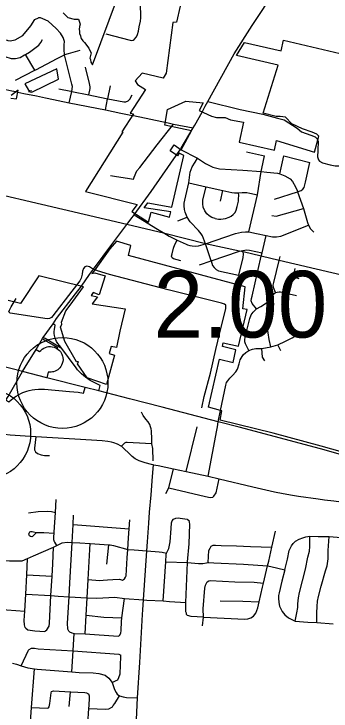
# Model space of a CAD drawing. Extents: x 1659811 to 1934326, y 644115 to 934867.
# Drawn here: x 1806794 to 1812018, y 688370 to 699875 of the extents above; entities that cross this region are included whole.
import ezdxf

# ---------------------------------------------------------------- set-up
doc = ezdxf.new("R2010")
doc.units = 0
for name, color, linetype in [('Default', 7, 'Continuous'), ('GM_X_City_Street', 7, 'Continuous'), ('GM_X_Corporation', 7, 'Continuous'), ('GM_X_County_Road', 7, 'Continuous'), ('GM_X_Interchange_Ramps', 7, 'Continuous'), ('GM_X_Interstate_Route', 7, 'Continuous'), ('GM_X_Township', 7, 'Continuous'), ('GM_X_Township_Road', 7, 'Continuous'), ('GM_X_US_Route', 7, 'Continuous')]:
    doc.layers.add(name, color=color, linetype=linetype)

msp = doc.modelspace()

# ---------------------------------------------------------------- linework, layer by layer
at = {"layer": 'Default'}
for centre in [(1807592, 693785), (1806318, 692948)]:
    msp.add_circle(centre, 750, dxfattribs=at)
at = {"layer": 'GM_X_City_Street'}
for points in [[(1808777, 699453), (1808814, 699499), (1808832, 699538), (1808844, 699592), (1808857, 699662), (1808877, 699755), (1808884, 699811), (1808886, 699883), (1808868, 700213), (1808881, 700265), (1808924, 700410), (1808950, 700522), (1809014, 700652)], [(1805586, 699203), (1805701, 699308), (1805749, 699339), (1805806, 699360), (1805921, 699380), (1805973, 699385), (1806322, 699422), (1806592, 699450), (1806680, 699441), (1806692, 699439), (1806732, 699433), (1806816, 699448), (1806942, 699519), (1807071, 699679), (1807140, 699782), (1807200, 699811)], [(1807705, 698411), (1807745, 698595), (1807756, 698677), (1807749, 698714), (1807690, 698934), (1807627, 699202), (1807625, 699208), (1807623, 699283), (1807622, 699367), (1807624, 699419), (1807603, 699488), (1807562, 699557), (1807492, 699637), (1807421, 699698), (1807358, 699756), (1807268, 699794), (1807230, 699811), (1807200, 699811)], [(1806970, 699199), (1806972, 699200), (1806986, 699208), (1807049, 699244), (1807201, 699362), (1807234, 699403), (1807265, 699453)], [(1808309, 699546), (1808711, 699442), (1808727, 699439), (1808759, 699445), (1808777, 699453)], [(1807140, 698949), (1806986, 699208)], [(1807626, 699202), (1807627, 699202), (1807631, 699204), (1807690, 699223), (1807883, 699275)], [(1806643, 699171), (1806748, 699142), (1806822, 699140), (1806894, 699155), (1806970, 699199)], [(1807151, 698955), (1807152, 698955), (1807504, 699139), (1807626, 699202)], [(1808030, 698543), (1808051, 698644), (1808048, 698670), (1808039, 698726), (1807974, 698996)], [(1806819, 698781), (1807140, 698949), (1807151, 698955)], [(1806536, 698655), (1806554, 698652), (1806759, 698606), (1806794, 698599)], [(1807535, 698641), (1807729, 698599)], [(1808337, 698469), (1808339, 698475), (1808385, 698691)], [(1806846, 698589), (1806856, 698586), (1806957, 698564), (1807168, 698522), (1807312, 698491)], [(1807729, 698599), (1807745, 698595), (1808030, 698543), (1808311, 698481)], [(1808311, 698481), (1808339, 698475), (1808604, 698423), (1808639, 698424), (1808675, 698440), (1808701, 698470), (1808744, 698541)], [(1807312, 698491), (1807342, 698485), (1807705, 698411), (1808302, 698291), (1808557, 698239)], [(1808302, 698291), (1808337, 698469)], [(1808557, 698239), (1808748, 698201), (1808764, 698197)], [(1809334, 698076), (1809425, 698057), (1809749, 697995)], [(1811791, 697808), (1811807, 697776), (1811801, 697621), (1811793, 697519), (1811810, 697469), (1811828, 697447), (1811876, 697420), (1812006, 697385), (1812086, 697370), (1812158, 697370), (1812246, 697351), (1812348, 697334), (1812465, 697343), (1812495, 697343), (1812529, 697331), (1812575, 697318), (1812623, 697304), (1812628, 697303), (1812634, 697302)], [(1809536, 697637), (1809820, 697493), (1809950, 697406), (1810071, 697349), (1810183, 697321), (1810566, 697297), (1810867, 697273), (1810960, 697266), (1811138, 697249), (1811174, 697236), (1811256, 697206), (1811344, 697153), (1811382, 697108), (1811431, 697024), (1811463, 696951), (1811465, 696940), (1811563, 696665), (1811628, 696432), (1811648, 696387), (1811682, 696326), (1811732, 696271)], [(1810626, 697602), (1810924, 697531)], [(1810042, 695801), (1809948, 696080), (1809900, 696211), (1809876, 696247), (1809835, 696302), (1809699, 696445), (1809645, 696520), (1809613, 696606), (1809603, 696650), (1809597, 696708), (1809598, 696751), (1809608, 696803), (1809677, 697087), (1809696, 697264), (1809731, 697352), (1809779, 697429), (1809820, 697493)], [(1810878, 697323), (1810878, 697327), (1810924, 697531)], [(1811174, 697236), (1811241, 697531), (1811669, 697421)], [(1811465, 696940), (1811527, 696961), (1811553, 696983), (1811573, 697009), (1811596, 697101), (1811669, 697421)], [(1810664, 696278), (1810805, 696889), (1810867, 697273), (1810878, 697323)], [(1809677, 697087), (1809958, 697020), (1810235, 696959), (1810382, 696928), (1810430, 696924), (1810493, 696924), (1810553, 696930), (1810629, 696927), (1810682, 696920), (1810805, 696889)], [(1810110, 696497), (1810056, 696518), (1810011, 696545), (1809974, 696578), (1809938, 696628), (1809913, 696685), (1809904, 696742), (1809907, 696808), (1809958, 697020)], [(1810110, 696497), (1810165, 696488), (1810200, 696487), (1810238, 696491), (1810279, 696500), (1810337, 696521), (1810373, 696539), (1810403, 696563), (1810436, 696599), (1810455, 696635), (1810471, 696697), (1810491, 696786), (1810496, 696826), (1810497, 696879), (1810493, 696924)], [(1810197, 696788), (1810235, 696959)], [(1811085, 696820), (1811465, 696940)], [(1811042, 696550), (1811112, 696536), (1811563, 696665)], [(1808776, 696560), (1809158, 696323), (1809281, 696250), (1809353, 696207), (1809483, 696144), (1809629, 696074), (1809653, 696065), (1809693, 696053), (1809732, 696046), (1809788, 696042), (1809834, 696046), (1809948, 696080), (1810443, 696251), (1810541, 696275), (1810610, 696279), (1810664, 696278), (1810792, 696253), (1810951, 696217), (1811053, 696197), (1811120, 696197), (1811189, 696208), (1811648, 696387)], [(1809495, 696459), (1809645, 696520)], [(1810790, 695006), (1810718, 695098), (1810703, 695139), (1810706, 695177), (1810716, 695219), (1810869, 695876), (1810883, 695934), (1810951, 696217)], [(1809541, 695798), (1809422, 695835), (1809401, 695852), (1809391, 695878), (1809398, 695914), (1809423, 696009), (1809445, 696070), (1809483, 696144)], [(1810044, 695802), (1810511, 695961), (1810564, 695973), (1810631, 695982), (1810675, 695978), (1810883, 695934)], [(1810492, 695563), (1810507, 695584), (1810570, 695857), (1810577, 695908), (1810570, 695947), (1810564, 695973)], [(1811101, 695276), (1811068, 695358), (1811066, 695398), (1811076, 695444), (1811163, 695807), (1811180, 695872)], [(1809849, 695737), (1810042, 695801), (1810044, 695802)], [(1810042, 695801), (1810067, 695722), (1810091, 695691), (1810127, 695660), (1810166, 695638), (1810492, 695563)], [(1808072, 695681), (1808037, 695704), (1807997, 695711), (1807963, 695701), (1807941, 695673), (1807925, 695628), (1807918, 695580), (1807899, 695512), (1807877, 695473), (1807825, 695401), (1807748, 695302)], [(1811328, 695254), (1811397, 695534), (1811426, 695673)], [(1811397, 695534), (1811490, 695511)], [(1810663, 694319), (1810639, 694362), (1810608, 694428), (1810599, 694464), (1810598, 694497), (1810604, 694539), (1810682, 694851), (1810704, 694907), (1810736, 694952), (1810790, 695006), (1810864, 695047), (1810940, 695094), (1810975, 695126), (1811001, 695158), (1811043, 695227), (1811074, 695258), (1811101, 695276)], [(1811101, 695276), (1811130, 695285), (1811162, 695289), (1811186, 695287), (1811328, 695254), (1811447, 695226)], [(1806750, 695042), (1806832, 695177)], [(1811026, 694380), (1810997, 694501), (1810964, 694721)], [(1810555, 694219), (1810572, 694251), (1810614, 694287), (1810663, 694319), (1810726, 694344), (1810781, 694352), (1810876, 694355), (1811026, 694380), (1811141, 694416), (1811269, 694476), (1811379, 694532), (1811471, 694592)], [(1811190, 694314), (1811141, 694416)], [(1810926, 694150), (1810891, 694213), (1810876, 694355)], [(1810196, 693333), (1810283, 693751), (1810296, 693791), (1810315, 693818), (1810349, 693863), (1810397, 693910), (1810452, 693969), (1810478, 694010), (1810505, 694103), (1810522, 694164), (1810555, 694219)], [(1809067, 692780), (1809065, 692881), (1809061, 692975), (1809059, 692996), (1809054, 693025), (1809046, 693059), (1809031, 693097), (1809004, 693143), (1808967, 693189), (1808924, 693250), (1808896, 693303)], [(1809996, 692244), (1810136, 693003), (1810146, 693060)], [(1808561, 692742), (1808500, 692775), (1808442, 692798), (1808400, 692809), (1808340, 692819), (1808246, 692828), (1808072, 692839), (1807153, 692896), (1806977, 692908), (1806733, 692925), (1806538, 692944), (1806430, 692955), (1806367, 692985)], [(1807153, 692896), (1807131, 692708), (1807133, 692680), (1807151, 692646), (1807181, 692620), (1807241, 692599), (1807297, 692589), (1807377, 692585)], [(1809090, 692500), (1809083, 692702), (1809067, 692780), (1808960, 692788), (1808658, 692800), (1808638, 692800), (1808614, 692791), (1808564, 692740)], [(1808812, 688229), (1808830, 688587), (1808866, 689170), (1808913, 689964), (1808919, 690043), (1808927, 690205), (1808981, 691013), (1808995, 691162), (1809018, 691472), (1809029, 691653), (1809054, 691938), (1809078, 692242), (1809095, 692432), (1809059, 692441), (1808957, 692468), (1808856, 692499), (1808792, 692532), (1808742, 692570), (1808680, 692630), (1808614, 692691), (1808564, 692740), (1808561, 692742)], [(1809095, 692432), (1809168, 692424), (1809422, 692365), (1809632, 692321), (1809996, 692244), (1810174, 692200), (1810728, 692068), (1811086, 691987), (1811230, 691959), (1811383, 691934), (1811480, 691918), (1811805, 691871)], [(1809294, 691959), (1809346, 692054), (1809422, 692365)], [(1809346, 692054), (1809951, 691911), (1810025, 691895), (1810070, 691901), (1810089, 691918), (1810124, 691971), (1810174, 692200)], [(1807501, 691102), (1807468, 691155), (1807462, 691163), (1807452, 691195), (1807451, 691243), (1807456, 691306), (1807457, 691320), (1807477, 691645), (1807491, 691862)], [(1811805, 691871), (1811910, 691856), (1812063, 691838), (1812187, 691822), (1812292, 691801), (1812327, 691789)], [(1807031, 691642), (1807191, 691662), (1807340, 691669), (1807410, 691661), (1807477, 691645)], [(1807708, 689675), (1807698, 689689), (1807684, 689723), (1807678, 689819), (1807704, 690257), (1807717, 690484), (1807751, 691152), (1807767, 691447), (1807775, 691604)], [(1808617, 690550), (1808634, 690577), (1808643, 690604), (1808658, 690896), (1808669, 691037), (1808681, 691228), (1808692, 691378), (1808703, 691528)], [(1809251, 690187), (1809295, 690833), (1809297, 690877), (1809300, 690909), (1809301, 690947), (1809307, 690978), (1809347, 691051), (1809369, 691160), (1809382, 691383), (1809388, 691477), (1809403, 691511), (1809422, 691535)], [(1809422, 691535), (1809459, 691556), (1809499, 691559), (1809532, 691556), (1809646, 691537), (1809654, 691531), (1809682, 691513)], [(1809915, 689918), (1809815, 689926), (1809711, 689930), (1809653, 689949), (1809639, 689961), (1809638, 689985), (1809628, 690010), (1809624, 690041), (1809623, 690083), (1809626, 690162), (1809652, 690820), (1809652, 690832), (1809679, 691129), (1809694, 691454), (1809684, 691489), (1809682, 691513)], [(1807767, 691447), (1808692, 691378)], [(1807164, 691317), (1807126, 691276), (1807098, 691248), (1807088, 691244), (1807069, 691249), (1807052, 691263), (1807042, 691277), (1807040, 691289), (1807042, 691303), (1807048, 691319), (1807058, 691329), (1807070, 691335), (1807094, 691335), (1807114, 691329), (1807164, 691317), (1807284, 691314), (1807456, 691306)], [(1809915, 689918), (1810599, 689888), (1810645, 689890), (1810697, 689906), (1810742, 689938), (1810780, 689986), (1810810, 690072), (1810834, 690172), (1810890, 690415), (1810905, 690480), (1810973, 690768), (1810992, 690845), (1811043, 691074), (1811104, 691340)], [(1806885, 690847), (1806929, 690847), (1807018, 690887), (1807115, 690929), (1807444, 691077), (1807501, 691102), (1807512, 691108), (1807587, 691145), (1807670, 691158), (1807751, 691152), (1807880, 691144), (1808047, 691134), (1808355, 691115), (1808380, 691114), (1808436, 691103), (1808669, 691037), (1808774, 691028), (1808981, 691013), (1809185, 690997), (1809238, 690990), (1809307, 690978)], [(1811258, 690702), (1811298, 690879), (1811329, 691022), (1811364, 691097), (1811396, 691137), (1811435, 691175), (1811492, 691207), (1811551, 691228), (1811605, 691247), (1811666, 691255), (1811804, 691250), (1811986, 691248), (1812251, 691229)], [(1811426, 689856), (1811457, 689991), (1811472, 690077), (1811471, 690138), (1811480, 690239), (1811498, 690327), (1811597, 690713), (1811638, 690907), (1811664, 691006), (1811669, 691086), (1811666, 691255)], [(1811783, 689830), (1811785, 689989), (1811788, 690097), (1811797, 690185), (1811811, 690261), (1811856, 690432), (1811929, 690684), (1811956, 690768), (1811969, 690880), (1811973, 691018), (1811986, 691248)], [(1807333, 689708), (1807373, 689772), (1807377, 689822), (1807404, 690275), (1807423, 690597), (1807435, 690798), (1807444, 691077)], [(1807967, 689642), (1807983, 689951), (1807999, 690238), (1808016, 690539), (1808047, 691134)], [(1808324, 690796), (1808355, 691115)], [(1809992, 690820), (1810007, 691018), (1810024, 691058), (1810042, 691090), (1810078, 691106), (1810112, 691110), (1810206, 691104), (1810461, 691097), (1810690, 691086), (1811043, 691074)], [(1805125, 690984), (1805373, 690847), (1805379, 690840), (1805415, 690832), (1805594, 690822), (1806057, 690806), (1806191, 690849), (1806269, 690869), (1806436, 690867), (1806442, 690867), (1806562, 690857), (1806722, 690849), (1806747, 690847), (1806877, 690847), (1806885, 690847)], [(1806987, 689735), (1806979, 689749), (1806970, 689793), (1806964, 689863), (1806972, 690018), (1806987, 690301), (1807004, 690616), (1807018, 690887)], [(1809295, 690833), (1809652, 690820), (1809834, 690804), (1809908, 690805), (1809967, 690817), (1809992, 690820), (1810007, 690821), (1810089, 690815), (1810574, 690794), (1810973, 690768), (1811027, 690758), (1811258, 690702)], [(1811258, 690702), (1811210, 690514), (1811164, 690322), (1811154, 690279), (1811153, 690233), (1811157, 690162), (1811171, 690103), (1811211, 690012), (1811257, 689960), (1811319, 689911), (1811426, 689856), (1811633, 689839), (1811783, 689830), (1812054, 689809)], [(1807004, 690616), (1807423, 690597)], [(1808016, 690539), (1808202, 690527), (1808265, 690529), (1808333, 690536), (1808423, 690540), (1808535, 690544), (1808583, 690529), (1808617, 690550)], [(1809899, 689777), (1809915, 689918), (1809910, 690058), (1809937, 690396), (1809947, 690450), (1809979, 690500), (1810002, 690518), (1810028, 690522), (1810433, 690503), (1810754, 690498), (1810905, 690480)], [(1806987, 690301), (1807404, 690275), (1807521, 690268), (1807704, 690257), (1807706, 690257), (1807995, 690238), (1807999, 690238), (1808159, 690234), (1808260, 690239), (1808454, 690249), (1808617, 690226), (1808927, 690205), (1808981, 690202), (1809251, 690187), (1809357, 690179), (1809626, 690162)], [(1806145, 690140), (1806204, 690091), (1806222, 690074), (1806276, 690070), (1806678, 690040), (1806972, 690018)], [(1808532, 689618), (1808554, 689656), (1808561, 689701), (1808565, 689849), (1808569, 689906), (1808617, 690226)], [(1810189, 690190), (1810564, 690181), (1810834, 690172)], [(1807983, 689951), (1808276, 689922), (1808569, 689906)], [(1806987, 689735), (1807022, 689711), (1807140, 689696), (1807301, 689684), (1807315, 689694), (1807333, 689708)], [(1807708, 689675), (1807746, 689661), (1807786, 689651), (1807967, 689642), (1808510, 689608), (1808532, 689618)], [(1807745, 689019), (1807767, 689361), (1807767, 689367), (1807786, 689651)], [(1806910, 689115), (1807031, 689373), (1807045, 689387), (1807084, 689406), (1807130, 689406), (1807192, 689399), (1807767, 689361), (1808522, 689310), (1808532, 689304), (1808552, 689292)], [(1808413, 688839), (1808477, 688872), (1808507, 688887), (1808523, 688921), (1808544, 688983), (1808556, 689269), (1808552, 689292)], [(1806769, 689160), (1806835, 689142), (1806910, 689115), (1807025, 689082), (1807134, 689067), (1807179, 689059), (1807745, 689019), (1807869, 689008), (1808100, 689000), (1808193, 688992), (1808295, 688960), (1808357, 688912), (1808413, 688839), (1808451, 688725), (1808477, 688675), (1808495, 688651), (1808534, 688621), (1808595, 688602), (1808650, 688592), (1808830, 688587)], [(1806990, 687840), (1807035, 687918), (1807051, 687964), (1807054, 688032), (1807085, 688429), (1807134, 689067)], [(1807085, 688429), (1807347, 688418), (1807364, 688422), (1807376, 688438), (1807384, 688496), (1807405, 688672), (1807415, 688690), (1807447, 688702), (1807726, 688685), (1807730, 688685), (1807961, 688674), (1807987, 688668), (1808011, 688657), (1808025, 688647)], [(1807455, 686053), (1807499, 687047), (1807515, 687113), (1807531, 687149), (1807544, 687179), (1807607, 687261), (1807695, 687336), (1807783, 687396), (1807871, 687457), (1807925, 687504), (1807948, 687546), (1807960, 687582), (1807971, 687648), (1808002, 688069), (1808009, 688158), (1808027, 688412), (1808031, 688464), (1808036, 688587), (1808036, 688615), (1808025, 688647)], [(1807703, 688444), (1807726, 688685)], [(1808027, 688412), (1808301, 688401), (1808357, 688409), (1808416, 688441), (1808430, 688460), (1808454, 688497), (1808534, 688621)]]:
    msp.add_lwpolyline(points, dxfattribs=at)
at = {"layer": 'GM_X_Corporation'}
for points in [[(1807603, 699891), (1807679, 699819), (1807787, 699791), (1807860, 699789), (1807883, 699707), (1807875, 699669), (1807868, 699620), (1807871, 699590), (1807874, 699572), (1807876, 699552), (1807888, 699514), (1807898, 699487), (1807902, 699469), (1807931, 699433), (1807954, 699403), (1808027, 699310), (1808038, 699284), (1808067, 699233), (1808046, 699148), (1808055, 699122), (1808061, 699082), (1808069, 699065), (1808088, 699033), (1808773, 700882)], [(1809531, 700005), (1809473, 699742), (1809414, 699732), (1809301, 698896), (1809253, 698817), (1808905, 698898), (1808793, 698770), (1808831, 698711), (1808962, 698626), (1808709, 698236), (1808761, 698224), (1808572, 697932), (1808586, 697923), (1807974, 696944), (1808825, 696732), (1808734, 696614), (1809013, 696441), (1809053, 696605), (1809358, 696523), (1809378, 696608), (1808941, 696675), (1808998, 696757), (1809396, 696686), (1809592, 697538), (1809517, 697577), (1809486, 697532), (1809365, 697614), (1809432, 697714), (1809548, 697634), (1809721, 697947), (1809280, 698041), (1809323, 698296), (1809628, 698434), (1809912, 698406), (1809846, 698283), (1810046, 698190), (1810133, 698168), (1810275, 698166), (1810363, 698130), (1810577, 698089), (1810507, 697760), (1811084, 697627), (1811117, 697787), (1811743, 697593), (1811818, 697858), (1811785, 697889), (1811706, 697924), (1811550, 697979), (1811370, 698061), (1811270, 698174), (1811181, 698180), (1811115, 698184), (1810899, 698237), (1811148, 699030), (1810460, 699191), (1810590, 699406), (1811195, 699264), (1811236, 699440), (1812356, 699179)], [(1806744, 698485), (1806838, 698477), (1806862, 698616), (1806750, 698530)], [(1812518, 692556), (1811855, 692744), (1811065, 692954), (1810190, 693173), (1810218, 693327), (1810196, 693333), (1809999, 693384), (1810180, 694175), (1810404, 694124), (1810452, 694334), (1810228, 694385), (1810243, 694448), (1810496, 694390), (1810635, 694995), (1810566, 695010), (1810604, 695371), (1808681, 695886), (1808722, 696054), (1808481, 696123), (1808372, 696001), (1808115, 695637), (1808079, 695589), (1808124, 695600), (1808299, 695553), (1808196, 695238), (1808101, 695276), (1808065, 695227), (1808171, 695208), (1808083, 695090), (1808628, 695008), (1808540, 694642), (1808481, 694368), (1808394, 694387), (1808365, 694272), (1808450, 694245), (1808318, 693757), (1807999, 693867), (1807842, 694099), (1807857, 694131), (1807822, 694134), (1807633, 694467), (1807559, 694706), (1807584, 694754), (1807575, 694789), (1807651, 694973), (1807721, 695071), (1807942, 695371), (1807204, 695555), (1806903, 695095), (1806697, 695146)]]:
    msp.add_lwpolyline(points, dxfattribs=at)
msp.add_lwpolyline([(1806974, 698722), (1807031, 698619), (1807083, 698608), (1807077, 698606), (1807031, 698596), (1807091, 698582), (1807528, 698800), (1807503, 698968)], close=True, dxfattribs=at)
at = {"layer": 'GM_X_County_Road'}
for points in [[(1806794, 698599), (1806846, 698589)], [(1808764, 698197), (1809334, 698076)]]:
    msp.add_lwpolyline(points, dxfattribs=at)
at = {"layer": 'GM_X_Interchange_Ramps'}
for points in [[(1808191, 693653), (1808215, 693744), (1808148, 693778), (1808093, 693804), (1808051, 693827), (1808010, 693853), (1807972, 693881), (1807939, 693907), (1807907, 693936), (1807868, 693975), (1807842, 694004), (1807817, 694035), (1807567, 694373), (1807545, 694403), (1807518, 694436), (1807497, 694471), (1807484, 694498), (1807475, 694523), (1807468, 694548), (1807463, 694570), (1807459, 694602), (1807459, 694632), (1807461, 694667), (1807474, 694739), (1807441, 694763)], [(1807264, 694519), (1807294, 694498), (1807512, 694368), (1807503, 694354)], [(1807567, 694373), (1807559, 694366), (1807306, 694517), (1807276, 694537)], [(1807159, 694338), (1807214, 694304), (1807234, 694323), (1807258, 694342), (1807284, 694358), (1807314, 694372), (1807340, 694380), (1807365, 694385), (1807394, 694386), (1807426, 694383), (1807458, 694375), (1807480, 694367), (1807503, 694354), (1807525, 694338), (1807544, 694321), (1807559, 694303), (1807572, 694284), (1807585, 694259), (1807595, 694229), (1807600, 694203), (1807602, 694165), (1807599, 694138), (1807590, 694106), (1807578, 694077), (1807564, 694054), (1807548, 694034), (1807531, 694017), (1807515, 694004), (1807495, 693992), (1807472, 693980), (1807447, 693971), (1807429, 693967), (1807406, 693964), (1807359, 693964), (1807335, 693869)], [(1806662, 693502), (1806711, 693473), (1806748, 693506), (1806775, 693527), (1806802, 693548), (1806829, 693566), (1806870, 693590), (1806907, 693610), (1806940, 693625), (1806972, 693637), (1807005, 693649), (1807042, 693660), (1807094, 693671), (1807140, 693679), (1807197, 693684), (1807248, 693685), (1807299, 693682), (1807707, 693646), (1807853, 693633), (1807941, 693616), (1807966, 693712)]]:
    msp.add_lwpolyline(points, dxfattribs=at)
at = {"layer": 'GM_X_Interstate_Route'}
for points in [[(1806933, 693974), (1806522, 694078), (1805650, 694296)], [(1814550, 691551), (1814371, 691658), (1813743, 692005), (1813454, 692129), (1812965, 692338), (1812503, 692508), (1811842, 692696), (1810502, 693057), (1810161, 693145), (1809234, 693383), (1808695, 693522), (1808191, 693653), (1807966, 693712), (1807335, 693869), (1806933, 693974)]]:
    msp.add_lwpolyline(points, dxfattribs=at)
at = {"layer": 'GM_X_Township'}
msp.add_lwpolyline([(1827950, 691856), (1821149, 693368), (1820279, 693511), (1817907, 694087), (1815708, 694629), (1815087, 694884), (1813506, 695256), (1811163, 695807), (1810869, 695876), (1810570, 695947), (1810511, 695961), (1809948, 696080), (1809281, 696250), (1808653, 696398), (1805040, 697248), (1799916, 698454), (1798676, 698746), (1796374, 699359), (1796095, 699426), (1795774, 699500), (1794871, 699722), (1794886, 700739)], dxfattribs=at)
at = {"layer": 'GM_X_Township_Road'}
for points in [[(1809986, 698432), (1810522, 698301), (1810892, 698219), (1811136, 698154), (1811246, 698125), (1811460, 697992), (1811531, 697932), (1811687, 697877), (1811757, 697846), (1811785, 697820), (1811787, 697816), (1811791, 697808)], [(1808383, 697211), (1808483, 697191), (1808663, 697163), (1808764, 697146), (1808773, 697181), (1808821, 697286), (1808866, 697342), (1808941, 697435), (1809153, 697713), (1809425, 698057)], [(1809889, 693372), (1809930, 693564), (1810030, 693949), (1810122, 694338), (1810212, 694726), (1810283, 695008), (1810286, 695042), (1810282, 695069), (1810263, 695086), (1810215, 695100), (1809336, 695322), (1808368, 695573), (1808168, 695635), (1808102, 695662), (1808072, 695681)], [(1807748, 695302), (1807437, 694894), (1807412, 694866), (1807380, 694846), (1807340, 694843), (1806729, 694939), (1806708, 694958), (1806718, 694988), (1806742, 695028), (1806750, 695042)], [(1810146, 693060), (1810161, 693145), (1810196, 693333)], [(1809632, 692321), (1809815, 693059)]]:
    msp.add_lwpolyline(points, dxfattribs=at)
at = {"layer": 'GM_X_US_Route'}
for points in [[(1810720, 699682), (1810774, 699768), (1811053, 700199), (1811362, 700675)], [(1809946, 698354), (1809986, 698432), (1810423, 699217), (1810720, 699682)], [(1809900, 698263), (1809946, 698354)], [(1809774, 698040), (1809896, 698255), (1809900, 698263)], [(1809549, 697658), (1809749, 697995), (1809774, 698040)], [(1808742, 696515), (1808776, 696560), (1809052, 696946), (1809518, 697612)], [(1809518, 697612), (1809536, 697637), (1809549, 697658)], [(1808406, 696068), (1808653, 696398), (1808742, 696515)], [(1808040, 695573), (1808102, 695662), (1808406, 696068)], [(1807809, 695257), (1807904, 695382), (1808040, 695573)], [(1806978, 694047), (1807159, 694338), (1807264, 694519), (1807276, 694537), (1807441, 694763), (1807494, 694846), (1807809, 695257)], [(1806538, 693288), (1806564, 693330), (1806662, 693502), (1806698, 693563), (1806933, 693974), (1806978, 694047)]]:
    msp.add_lwpolyline(points, dxfattribs=at)

# ---------------------------------------------------------------- texts
at = {"layer": 'Default'}
msp.add_text('2.00', height=1100, dxfattribs=at).set_placement((1809094, 694535))

doc.saveas('drawing.dxf')
